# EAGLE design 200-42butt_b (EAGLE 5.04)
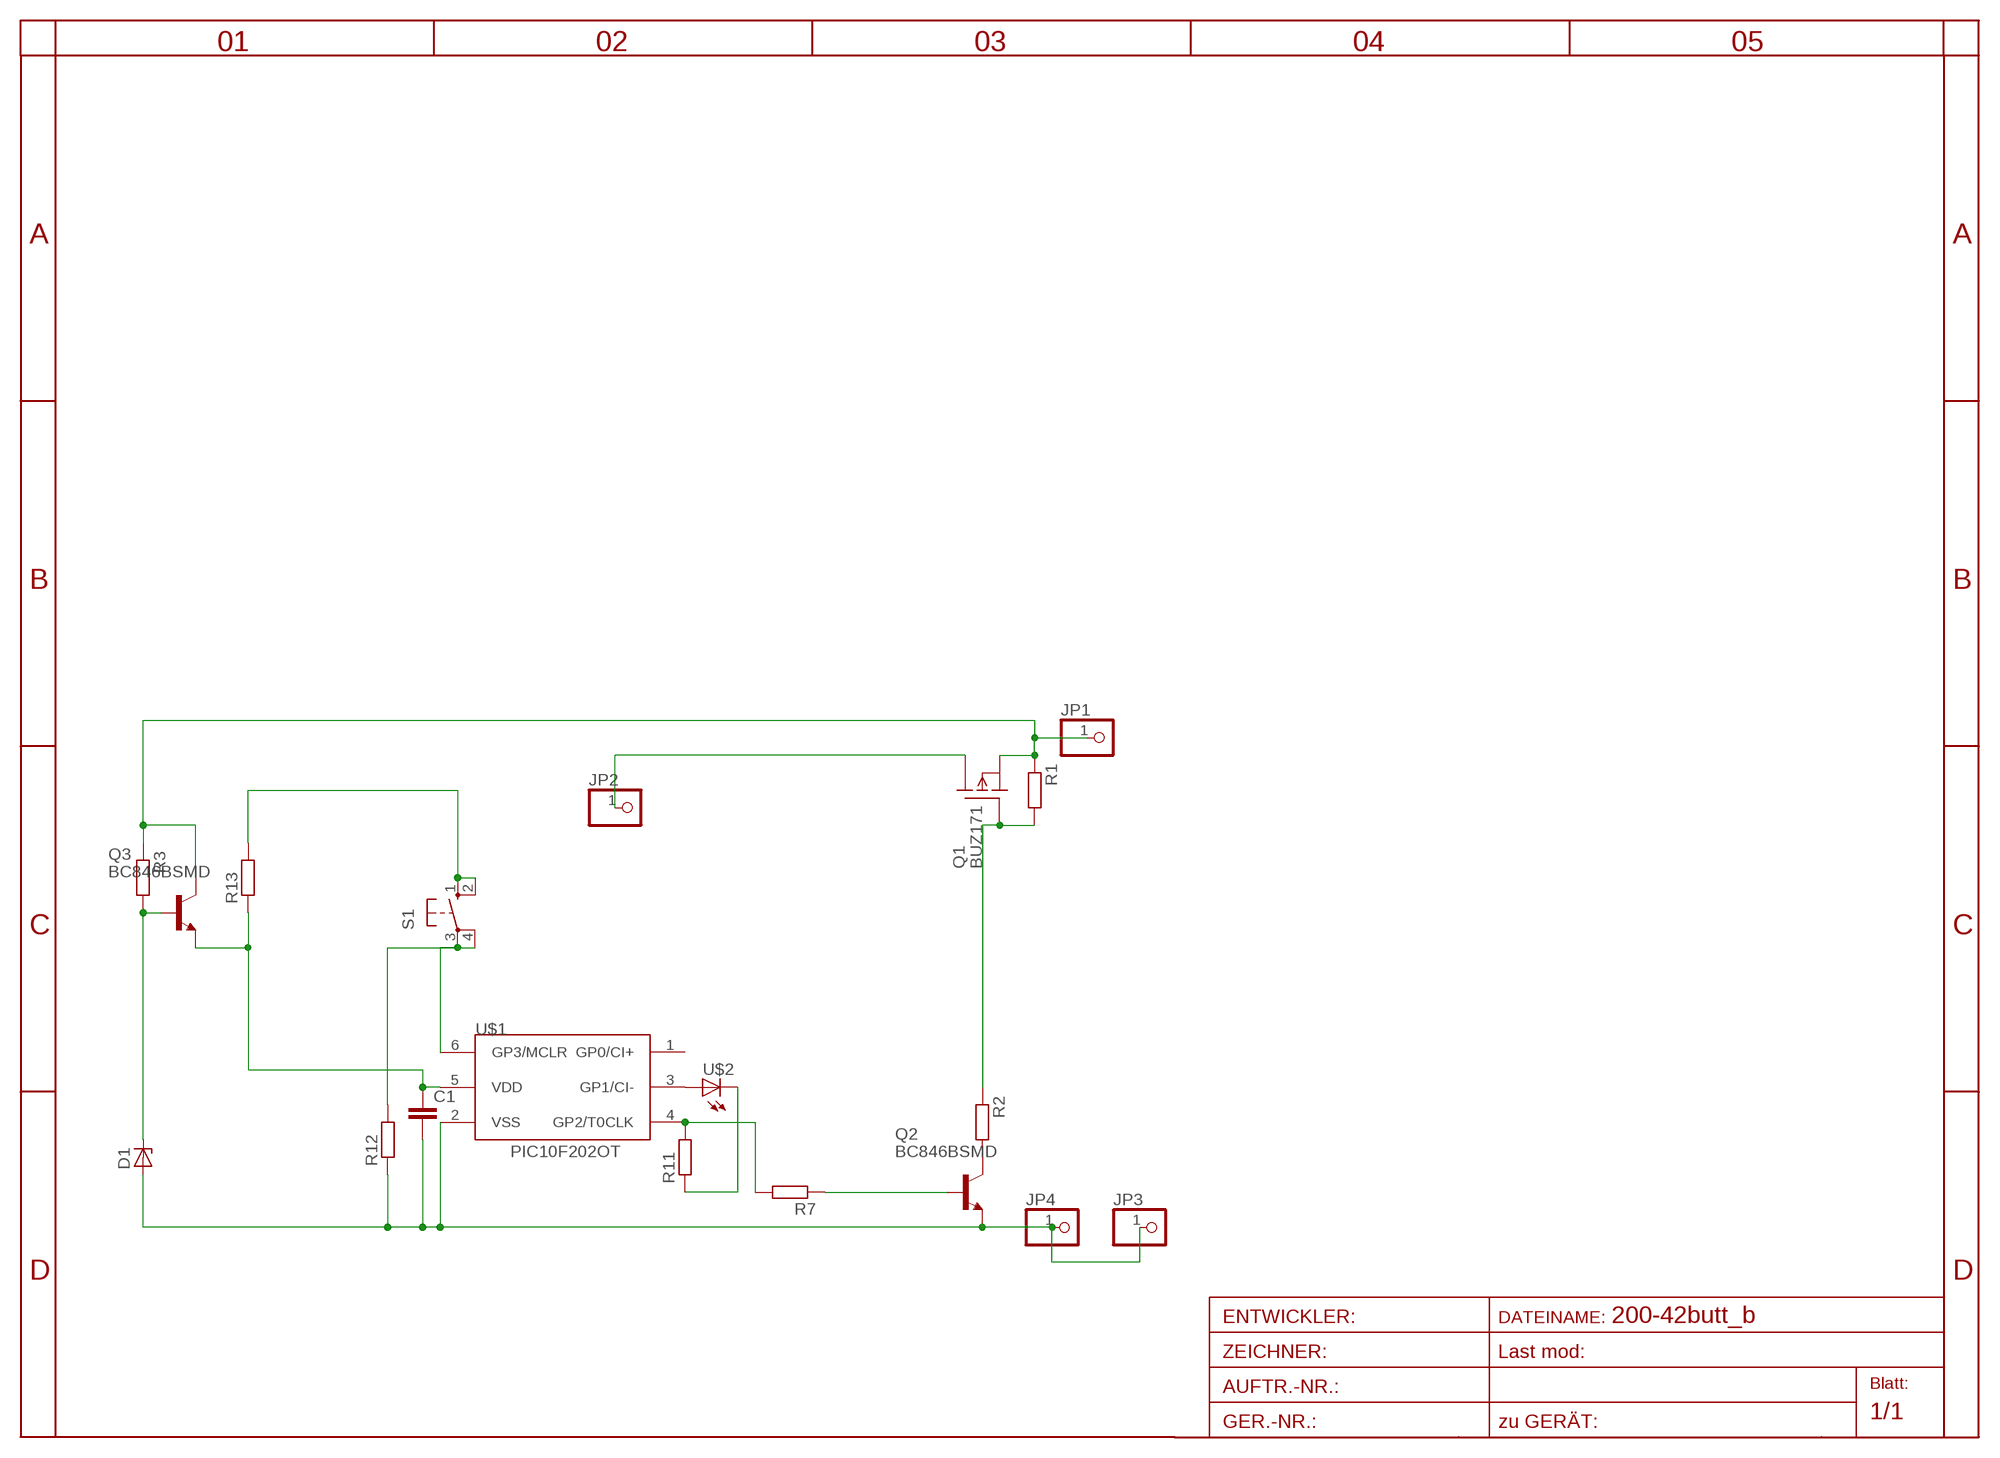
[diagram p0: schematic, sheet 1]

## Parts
C1  C-EUC1206  [C1206]
D1  ZENER-DIODESOT23  [SOT23]
JP1  PINHD-1X1  [1X01]
JP2  PINHD-1X1  [1X01]
JP3  PINHD-1X1  [1X01]
JP4  PINHD-1X1  [1X01]
Q1  BUZ171  [TO220]
Q2  BC846BSMD  [SOT23]
Q3  BC846BSMD  [SOT23]
R1  R-EU_R1206  [R1206]
R2  R-EU_R0805  [R0805]
R3  R-EU_R0805  [R0805]
R7  R-EU_R0805  [R0805]
R11  R-EU_R0805  [R0805]
R12  R-EU_R0805  [R0805]
R13  R-EU_R0805  [R0805]
S1  10-XX  [B3F-10XX]
U$1  PIC10F202OT  [SOT23-6]
U$2  LED3MM  [LED3MM]

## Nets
GND: C1.2 D1.1(A) JP3.1 JP4.1 Q2.2(E) R12.1 U$1.2(VSS)
N$2: C1.1 Q3.2(E) R13.1 U$1.5(VDD)
N$3: Q2.3(C) R2.2
N$4: D1.3(C) Q3.1(B) R3.2
N$5: U$1.3(GP1/CI-) U$2.A
N$6: R11.1 U$2.K(C)
N$7: Q1.1(G) R1.2 R2.1
N$9: R7.2 R11.2 U$1.4(GP2/T0CLK)
N$10: Q2.1(B) R7.1
N$11: R12.2 S1.3(P) S1.4(P1) U$1.6(GP3/MCLR)
N$15: R13.2 S1.1(S) S1.2(S1)
V+IN: JP1.1 Q1.3(S) Q3.3(C) R1.1 R3.1
V+OUT: JP2.1 Q1.2(D)
Unconnected: U$1.1(GP0/CI+)

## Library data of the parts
C1 = rcl:C-EU: CAPACITOR, European symbol
D1 = diode-1:ZENER-DIODE: Z-Diode
JP1-JP4 = pinhead:PINHD-1X1: PIN HEADER
Q1 = transistor-fet:BUZ171: P-Channel Enhancement MOSFET -50V; 7A; 0,4Ohm
Q2 Q3 = transistor-npn:BC846*: NPN Transistor
R1-R3 R7 R11-R13 = rcl:R-EU_: RESISTOR, European symbol
S1 = switch-omron:10-XX: OMRON SWITCH
U$1 = microchip-5:PIC10F2*: uPC nW 0,25/0,5k Program Flash memory Comparator
U$2 = led(2):LED: LED

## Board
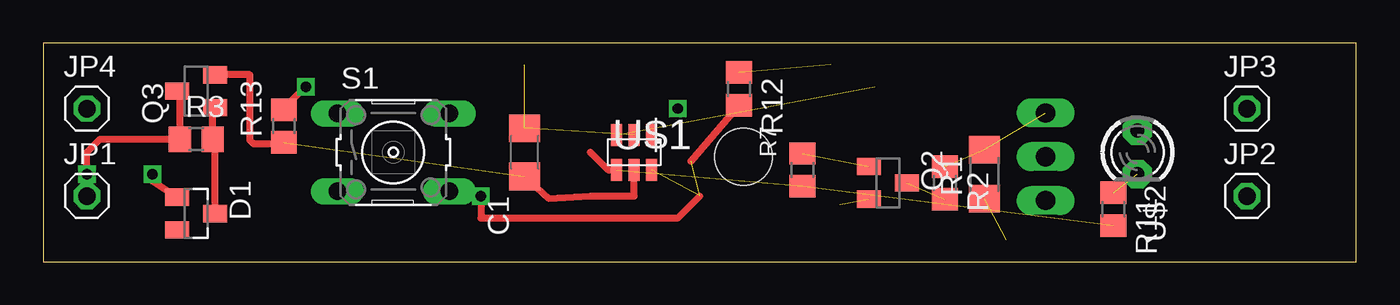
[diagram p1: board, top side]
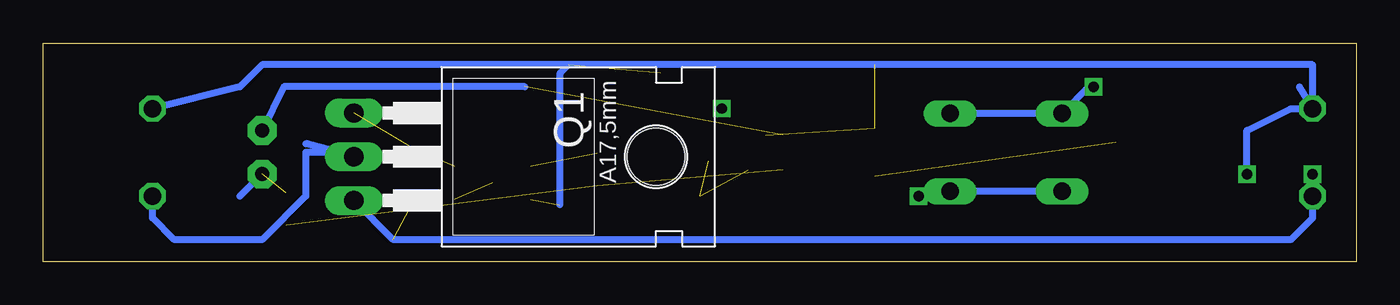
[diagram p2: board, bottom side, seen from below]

Size 76.2 x 12.7 mm. Coordinates in mm from the lower left corner, seen from the top.
Outline: 0,0 76.2,0 76.2,12.7 0,12.69 0,0
Copper layers (1*16): Top 0.035mm / dielectric 1.5mm / Bottom 0.035mm
Design rules "default": minimum track width 10mil, minimum drill 24mil, track to track 8mil, track to pad 8mil, pad to pad 8mil, via to via 8mil, smd to smd 8mil, copper to edge 40mil, drill to drill 8mil, minimum pad ring 10mil, minimum via ring 8mil, stop-mask expansion 4mil, vias tented up to drill 0mil, thermal gap 10mil

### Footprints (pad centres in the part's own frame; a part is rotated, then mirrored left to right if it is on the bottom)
C1206 = smd 1.6 x 1.8: 1 -1.4,0; 2 1.4,0
SOT23 = smd 1 x 1.4: 1 -0.95,-1.1; 2 0.95,-1.1; 3 0,1.1
1X01 = drill 1.016 octagon: 1 0,0
TO220 = drill 1.118 long: 1 -2.54,-6.35; 2 0,-6.35; 3 2.54,-6.35 | hole 3.302: 0,11.176
R1206 = smd 1.6 x 1.803: 1 -1.422,0; 2 1.422,0
R0805 = smd 1.3 x 1.5: 1 -0.95,0; 2 0.95,0
B3F-10XX = drill 1.016 long: 1 -3.251,2.261; 2 3.251,2.261; 3 -3.251,-2.261; 4 3.251,-2.261
SOT23-6 = smd 0.635 x 1.27: 1 -1.016,-1.016; 2 0,-1.016; 3 1.016,-1.016; 4 1.016,1.016; 5 0,1.016; 6 -1.016,1.016
LED3MM = drill 0.813 pad 1.676 octagon: A -1.27,0; K 1.27,0

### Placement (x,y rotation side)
C1  27.94,6.35 90 top
D1  8.89,2.79 270 top
JP1  2.54,3.81 0 top
JP2  69.85,3.81 0 top
JP3  69.85,8.89 0 top
JP4  2.54,8.89 0 top
Q1  51.82,6.1 270 bottom
Q2  49.02,4.57 270 top
Q3  8.89,9.91 90 top
R1  54.61,5.08 90 top
R2  52.32,4.57 270 top
R3  8.89,7.11 0 top
R7  44.07,5.33 270 top
R11  62.1,3.05 270 top
R12  40.39,10.03 270 top
R13  13.97,7.87 90 top
S1  20.32,6.35 0 top
U$1  34.29,6.35 180 top
U$2  63.5,6.35 270 top

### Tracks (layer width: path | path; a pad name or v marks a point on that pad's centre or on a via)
GND  (via drill 0.6)  (4 unrouted)
  Top 0.406: v6.35,5.08 6.35,4.68 D1.1
  Bottom 0.406: JP4.1 2.54,11.43 27.94,11.43 45.72,11.43 | JP3.1 64.77,10.16 63.5,11.43 45.72,11.43 | JP4.1 3.3,10.16 | 46.23,3.3 46.23,10.92 45.72,11.43 | JP4.1 3.81,8.89 6.35,7.62 v6.35,5.08
N$1  (via drill 0.6)
  other vias: 36.83,8.89
N$2  (1 unrouted)
  Top 0.406: Q3.2 12,10.86 12,7.05 12.19,6.86 13.9,6.86 R13.1 | C1.1 29.34,3.68 31.75,3.81 34.29,3.81 U$1.5
N$3  (1 unrouted)
N$4
  Top 0.406: D1.3 9.99,6.96 R3.2 9.84,8.81 Q3.1
N$5  (1 unrouted)
  Bottom 0.406: U$2.A 62.23,10.16 48.26,10.16
N$6  (1 unrouted)
  Bottom 0.406: 64.77,3.81 U$2.K
N$7  (2 unrouted)
N$9  (2 unrouted)
  Top 0.406: U$1.4 32.77,5.33 31.75,6.35
N$10  (1 unrouted)
N$11  (via drill 0.6)  (2 unrouted)
  Top 0.406: v25.4,3.81 25.4,2.54 36.83,2.54 38.1,3.81 | 37.59,5.84 R12.2
  Bottom 0.406: S1.3 S1.4 25.12,4.09 v25.4,3.81
N$15  (via drill 0.6)
  Top 0.406: R13.2 13.97,8.89 v15.24,10.16
  Bottom 0.406: v15.24,10.16 15.52,10.16 S1.1 S1.2
V+IN  (via drill 0.6)  (1 unrouted)
  Top 0.406: v2.54,5.08 2.54,6.35 3.3,7.11 R3.1 7.94,9.76 Q3.3
  Bottom 0.406: Q1.3 55.88,1.27 3.81,1.27 2.54,2.54 JP1.1 v2.54,5.08
V+OUT
  Bottom 0.406: 60.96,6.86 Q1.2 58.42,6.35 60.96,6.35 60.96,3.81 63.5,1.27 68.58,1.27 69.85,2.54 JP2.1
